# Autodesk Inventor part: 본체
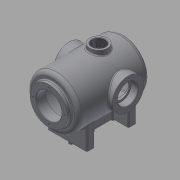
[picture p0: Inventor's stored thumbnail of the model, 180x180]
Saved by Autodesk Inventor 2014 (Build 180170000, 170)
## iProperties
Created: 2016-02
Part Number: 본체
Material: 일반
Document SubType Name: Modeling
Designer: mduedu
Density: 2.71 g/cm^3
Appearance: 기본값
Author: mduedu
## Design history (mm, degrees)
sketch "스케치2"
  geometry: L1 (0, 100)-(0, -100); L2 (65, -75.993)-(65, 100); L3 (65, 100)-(0, 100); A1 r 100 centre (0, 0) between (0, -100) and (65, -75.993); 2 further points
  constraints: 6 end point, 2 midpoint, 2 point on circle, 1 centre point, 1 coincident, 1 horizontal, 1 parallel, 1 vertical
  dimensions: "d3" = 200 distance of L1.start L1.end; "d5" = 130 diameter of L2 L1; "d6" = 100 radius of A1
revolve "회전1" sketch "스케치2" stored, may be unused: angle "d7" = 90 deg
sketch "스케치3"
  geometry: C1 r 47.5 at (0, 0); 1 further point
  constraints: 1 centre point, 1 coincident
  dimensions: "d8" = 95 diameter of C1
extrude "돌출2" join sketch "스케치3" distance "d10" = 10; taper "d11" = 0 deg
sketch "스케치5"
  geometry: L1 (47.5, 110)-(47.5, 100) reference; L2 (47.5, 100)-(65, 100) reference; L3 (65, 100)-(65, -75.993) reference; L4 (-65, -75.993)-(-65, 100) reference; L5 (-65, 100)-(-47.5, 100) reference; L6 (-47.5, 100)-(-47.5, 110) reference; L7 (-47.5, 110)-(47.5, 110) reference; L8 (55, 85)-(55, -71.239); L9 (0, 85)-(55, 85); L10 (0, 85)-(0, -90); A1 r 100 centre (0, 0) between (0, -100) and (65, -75.993) reference; A2 r 100 centre (0, 0) between (-65, -75.993) and (0, -100) reference; A3 r 90 centre (0, 0) between (0, -90) and (55, -71.239); 1 further point
  constraints: 6 end point, 2 point on circle, 1 centre point, 1 parallel, 1 perpendicular, 1 point on line, 1 vertical
  dimensions: "d13" = 10 distance between parallel lines of L3 L8; "d14" = 10 radial gap between concentric circles of A3 A1; "d15" = 15 distance between parallel lines of L9 L2
revolve "회전2" sketch "스케치5" stored, may be unused: angle "d16" = 90 deg
hole "구멍1" diameter "d19" = 65; stored, may be unused: countersink angle "d23" = 90 deg, drill point angle "d25" = 118 deg; dims "d17" = 10, "d18" = 10, "d20" = 6, "d21" = 4, "d22" = 2, "d24" = 8
node "작업 평면1"
sketch "스케치6"
  geometry: L1 (47.5, 110)-(-47.5, 110) reference; C1 r 40 at (0, -17); 1 further point
  constraints: 1 centre point, 1 vertical alignment
  dimensions: "d27" = 80 diameter of C1; "d29" = 127 distance from line of C1.centre L1
extrude "돌출3" join sketch "스케치6" stored distance "d30" = 10; taper "d31" = 0 deg
hole "구멍2" diameter "d34" = 42; stored, may be unused: countersink angle "d38" = 90 deg, drill point angle "d40" = 118 deg; dims "d32" = 10, "d33" = 10, "d35" = 6, "d36" = 52, "d37" = 18, "d39" = 8
sketch "스케치7" dims "d41" = 65
  geometry: C1 r 40 at (0, 0) reference; 3 further points
  constraints: 2 vertical alignment, 1 coincident, 2 other
hole "구멍3" sketch "스케치7" at (0, 32.5) diameter "d43" = 3.242; stored, may be unused: countersink angle "d47" = 90 deg, drill point angle "d49" = 118 deg; dims "d44" = 11, "d45" = 13, "d46" = 18, "d48" = 13
sketch "스케치8" dims "d53" = 80
  geometry: 3 further points
  constraints: 2 vertical alignment, 1 coincident, 2 other
hole "구멍4" sketch "스케치8" at (0, 40) diameter "d56" = 3.242; stored, may be unused: countersink angle "d60" = 90 deg, drill point angle "d62" = 118 deg; dims "d57" = 11, "d58" = 13, "d59" = 18, "d61" = 13
fillet "모깎기1" dims "d66" = 10
fillet "모깎기2" dims "d67" = 3
fillet "모깎기3" dims "d68" = 0.3
chamfer "모따기1" distance "d69" = 1; stored, may be unused: second distance "d70" = 2, angle "d71" = 45 deg
node "작업 평면5"
sketch "스케치10"
  geometry: L1 (-50, -63)-(50, -63); L2 (50, -63)-(50, -43); L3 (50, -43)-(-50, -43); L4 (-50, -43)-(-50, -63); L5 (-50, 0)-(50, 0); L6 (-50, 63)-(50, 63); L7 (50, 63)-(50, 43); L8 (50, 43)-(-50, 43); L9 (-50, 43)-(-50, 63); 2 further points
  constraints: 18 end point, 4 symmetric about line, 2 parallel, 2 perpendicular, 1 coincident, 1 horizontal, 1 midpoint
  dimensions: "d80" = 20 distance of L3.end L1.start; "d82" = 100 distance of L1.start L1.end; "d130" = 43 vertical distance of L3.end point (0, 0); "d131" = 50 horizontal distance of L3.end point (0, 0); "d132" = 100 distance of L5.start L5.end
extrude "돌출5" join sketch "스케치10" stored distance "d84" = 10; taper "d85" = 0 deg
sketch "스케치11"
  geometry: L1 (-100, -43)-(-100, 43); L2 (-65, 90)-(-65, -71.239) reference; L3 (-100, -43)-(-41.533, -43) reference; L4 (-100, 43)-(-41.533, 43) reference; 1 further point
  constraints: 2 end point, 1 point on line, 1 vertical
feature "리브1" sketch "스케치11" dims "d88" = 1, "d89" = 20, "d90" = 0, "d91" = 0, "d92" = 1, "d93" = 1
fillet "모깎기18" dims "d179" = 3
fillet "모깎기19" dims "d180" = 3
fillet "모깎기20" dims "d181" = 3
fillet "모깎기21" dims "d182" = 3
fillet "모깎기16" dims "d167" = 3
fillet "모깎기17" dims "d168" = 3
node "작업 평면6"
sketch "스케치19"
  geometry: L1 (75, -57)-(75, 23) reference; L2 (-75, -57)-(-75, 23) reference; L3 (75, -17)-(-75, -17); C1 r 22.5 at (0, -17); 1 further point
  constraints: 3 midpoint, 2 end point, 1 centre point
  dimensions: "d149" = 45 diameter of C1
extrude "돌출11" join sketch "스케치19" stored distance "d150" = 10; taper "d151" = 0 deg
hole "구멍6" diameter "d154" = 33.376; stored, may be unused: countersink angle "d158" = 90 deg, drill point angle "d160" = 118 deg; dims "d155" = 6, "d156" = 4, "d157" = 2, "d159" = 8, "d177" = 10, "d178" = 10
fillet "모깎기11" dims "d161" = 3
chamfer "모따기3" distance "d164" = 1; stored, may be unused: second distance "d165" = 2, angle "d166" = 45 deg
sketch "스케치20"
  geometry: L1 (10, 40)-(10, -40) reference; L2 (13, -43)-(47, -43) reference; L3 (-10, -40)-(-10, 40) reference; L4 (47, 43)-(13, 43) reference; L5 (-40, 53)-(40, 53); L6 (-40, -53)-(40, -53); L7 (0, 53)-(0, -53); L8 (50, -46)-(50, -60) reference; L9 (47, -63)-(-47, -63) reference; L10 (-50, -60)-(-50, -46) reference; L11 (-47, -43)-(-13, -43) reference; L12 (-13, 43)-(-47, 43) reference; L13 (-50, 46)-(-50, 60) reference; L14 (-47, 63)-(47, 63) reference; L15 (50, 60)-(50, 46) reference; C1 r 5 at (0, 53); C2 r 5 at (0, 0); C3 r 5 at (0, -53); A1 r 3 centre (13, -40) between (10, -40) and (13, -43) reference; A2 r 3 centre (-13, -40) between (-13, -43) and (-10, -40) reference; A3 r 3 centre (-13, 40) between (-10, 40) and (-13, 43) reference; A4 r 3 centre (13, 40) between (13, 43) and (10, 40) reference; A5 r 3 centre (47, -46) between (50, -46) and (47, -43) reference; A6 r 3 centre (47, -60) between (47, -63) and (50, -60) reference; A7 r 3 centre (-47, -60) between (-50, -60) and (-47, -63) reference; A8 r 3 centre (-47, -46) between (-47, -43) and (-50, -46) reference; A9 r 3 centre (-47, 46) between (-50, 46) and (-47, 43) reference; A10 r 3 centre (-47, 60) between (-47, 63) and (-50, 60) reference; A11 r 3 centre (47, 60) between (50, 60) and (47, 63) reference; A12 r 3 centre (47, 46) between (47, 43) and (50, 46) reference; 1 further point
  constraints: 6 end point, 3 centre point, 3 coincident, 2 midpoint, 2 parallel
  dimensions: "d169" = 10 diameter of C1; "d170" = 10 diameter of C2; "d171" = 10 diameter of C3
extrude "돌출12" join sketch "스케치20" distance "d172" = 10; taper "d173" = 0 deg
chamfer "모따기4" distance "d174" = 1; stored, may be unused: second distance "d175" = 2, angle "d176" = 45 deg
node "솔리드2"
pattern_circular "원형 패턴1" dims angle "d51" = 360 deg
mirror "대칭1"
pattern_circular "원형 패턴2" dims angle "d64" = 360 deg
node "절단 모서리 투영1"
node "절단 모서리 투영4"
other parameters: "d26" = 75, "d136" = 175
